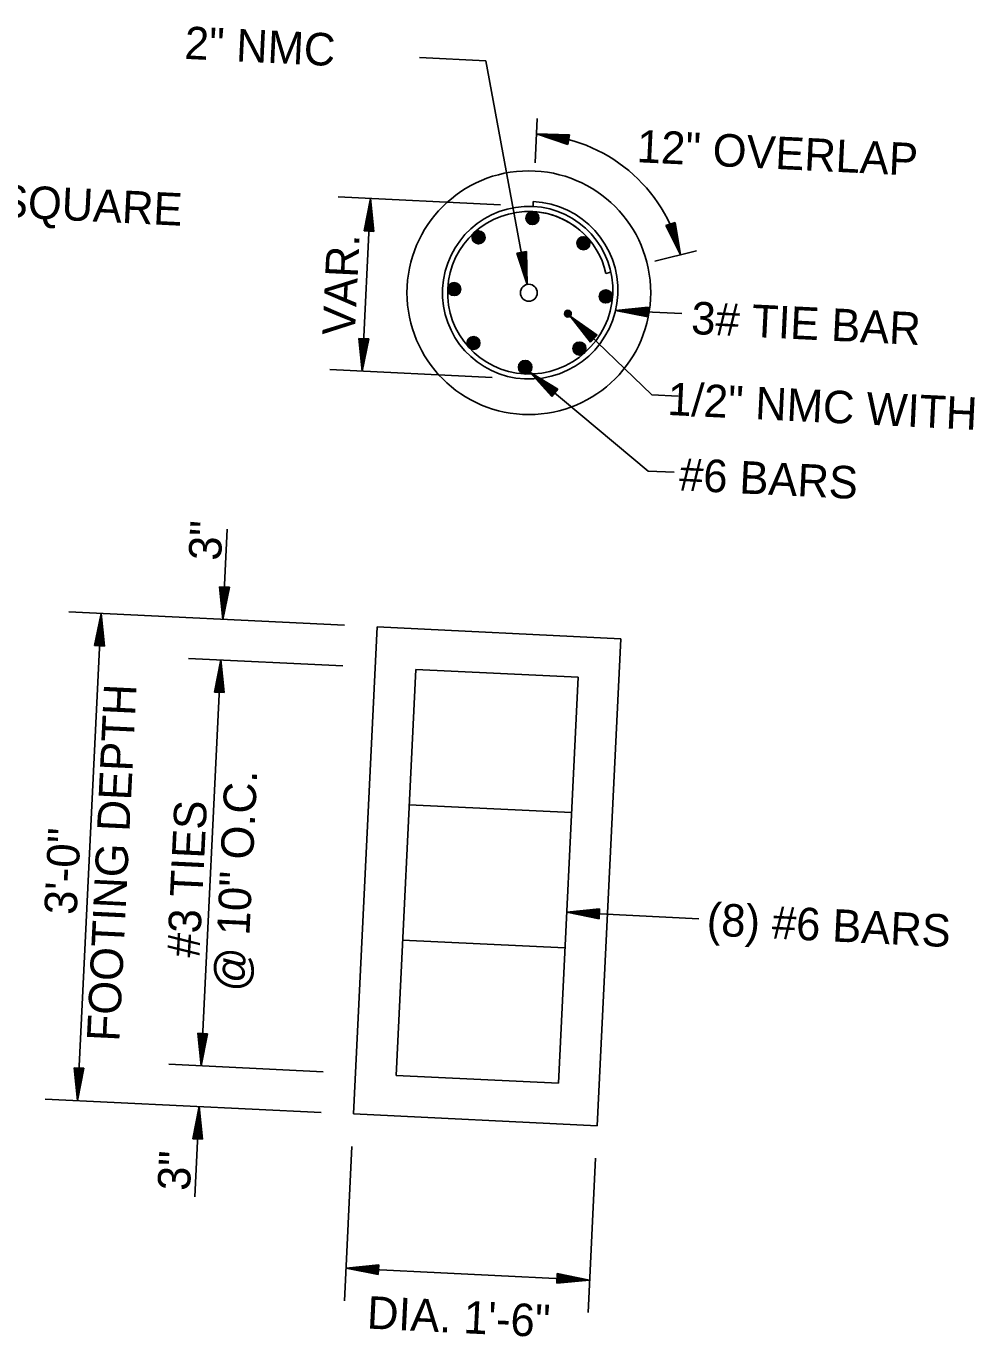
# Model space of a CAD drawing. Extents: x 661018 to 663325, y 642537 to 643074.
# Drawn here: x 662064.8 to 662163.6, y 642766 to 642901.8 of the extents above; entities that cross this region are included whole.
import ezdxf

# ---------------------------------------------------------------- set-up
doc = ezdxf.new("R2010")
doc.units = 0
doc.layers.add('R_Dimension', color=7, linetype='Continuous')

msp = doc.modelspace()

# ---------------------------------------------------------------- linework, layer by layer
at = {"layer": 'R_Dimension'}
for p, q in [((662105.59, 642898.58), (662112.48, 642898.24)), ((662116.77, 642875.08), (662112.48, 642898.24)), ((662117.58, 642887.68), (662117.8, 642892.28)), ((662120.96, 642889.59), (662117.73, 642890.67)), ((662121.14, 642890.58), (662117.73, 642890.67)), ((662120.97, 642889.67), (662118.28, 642890.57)), ((662121.12, 642890.5), (662118.28, 642890.57)), ((662121.11, 642890.41), (662118.85, 642890.47)), ((662120.99, 642889.75), (662118.85, 642890.47)), ((662121, 642889.84), (662119.41, 642890.38)), ((662121.09, 642890.33), (662119.41, 642890.38)), ((662120.96, 642889.59), (662121.14, 642890.58)), ((662121.08, 642890.25), (662119.97, 642890.28)), ((662121.02, 642889.92), (662119.97, 642890.28)), ((662121.06, 642890.16), (662120.52, 642890.18)), ((662121.03, 642890.01), (662120.52, 642890.18)), ((662114, 642883.32), (662097.17, 642884.14)), ((662099.67, 642866.09), (662100.53, 642883.97)), ((662099.87, 642880.63), (662100.53, 642883.97)), ((662100.88, 642880.58), (662100.53, 642883.97)), ((662117.36, 642883.16), (662117.39, 642883.68)), ((662099.95, 642880.63), (662100.51, 642883.41)), ((662100.04, 642880.63), (662100.48, 642882.83)), ((662100.12, 642880.62), (662100.45, 642882.27)), ((662100.62, 642880.6), (662100.45, 642882.27)), ((662100.71, 642880.59), (662100.48, 642882.83)), ((662100.79, 642880.59), (662100.51, 642883.41)), ((662116.63, 642881.96), (662117.36, 642882.63)), ((662116.64, 642882.08), (662117.24, 642882.63)), ((662116.64, 642881.85), (662117.47, 642882.61)), ((662116.66, 642881.76), (662117.56, 642882.58)), ((662116.69, 642882.25), (662117.07, 642882.59)), ((662116.69, 642881.67), (662117.64, 642882.54)), ((662116.73, 642881.6), (662117.71, 642882.49)), ((662116.78, 642881.53), (662117.78, 642882.43)), ((662116.84, 642881.47), (662117.83, 642882.37)), ((662116.9, 642881.41), (662117.88, 642882.3)), ((662116.98, 642881.37), (662117.92, 642882.22)), ((662100.21, 642880.62), (662100.42, 642881.7)), ((662100.29, 642880.61), (662100.4, 642881.14)), ((662100.45, 642880.61), (662100.4, 642881.14)), ((662100.54, 642880.6), (662100.42, 642881.7)), ((662117.06, 642881.33), (662117.95, 642882.14)), ((662117.15, 642881.3), (662117.97, 642882.04)), ((662117.26, 642881.28), (662117.98, 642881.93)), ((662117.39, 642881.29), (662117.96, 642881.8)), ((662117.58, 642881.34), (662117.89, 642881.62)), ((662132.09, 642881.5), (662131.13, 642881.19)), ((662131.13, 642881.19), (662132.66, 642878.14)), ((662131.21, 642881.21), (662132.48, 642878.68)), ((662131.29, 642881.24), (662132.3, 642879.23)), ((662131.37, 642881.27), (662132.13, 642879.76)), ((662131.45, 642881.29), (662131.95, 642880.3)), ((662131.53, 642881.32), (662131.77, 642880.84)), ((662131.68, 642881.37), (662131.77, 642880.84)), ((662131.76, 642881.39), (662131.95, 642880.3)), ((662131.85, 642881.42), (662132.13, 642879.76)), ((662131.93, 642881.45), (662132.3, 642879.23)), ((662132.01, 642881.48), (662132.48, 642878.68)), ((662132.09, 642881.5), (662132.66, 642878.14)), ((662099.87, 642880.63), (662100.88, 642880.58)), ((662111.05, 642880.02), (662111.72, 642880.63)), ((662111.05, 642879.9), (662111.84, 642880.62)), ((662111.06, 642879.8), (662111.93, 642880.59)), ((662111.08, 642880.16), (662111.58, 642880.62)), ((662111.09, 642879.71), (662112.02, 642880.56)), ((662111.13, 642879.63), (662112.1, 642880.51)), ((662111.17, 642879.56), (662112.16, 642880.46)), ((662111.19, 642880.38), (662111.35, 642880.52)), ((662111.23, 642879.5), (662112.22, 642880.4)), ((662111.29, 642879.44), (662112.28, 642880.34)), ((662111.36, 642879.39), (662112.32, 642880.26)), ((662111.43, 642879.34), (662112.35, 642880.18)), ((662111.52, 642879.31), (662112.38, 642880.09)), ((662111.62, 642879.29), (662112.39, 642879.99)), ((662111.74, 642879.28), (662112.39, 642879.87)), ((662111.89, 642879.3), (662112.35, 642879.72)), ((662121.91, 642879.32), (662122.68, 642880.02)), ((662121.92, 642879.44), (662122.56, 642880.03)), ((662121.92, 642879.22), (662122.78, 642880)), ((662121.95, 642879.59), (662122.41, 642880)), ((662121.95, 642879.13), (662122.87, 642879.96)), ((662121.98, 642879.05), (662122.95, 642879.92)), ((662122.03, 642878.97), (662123.02, 642879.87)), ((662122.08, 642878.91), (662123.08, 642879.81)), ((662122.14, 642878.85), (662123.13, 642879.75)), ((662122.21, 642878.79), (662123.18, 642879.67)), ((662122.28, 642878.75), (662123.21, 642879.59)), ((662122.37, 642878.71), (662123.24, 642879.51)), ((662116.67, 642878.49), (662115.68, 642878.31)), ((662115.68, 642878.31), (662116.77, 642875.08)), ((662115.76, 642878.32), (662116.67, 642875.63)), ((662115.84, 642878.34), (662116.57, 642876.2)), ((662115.93, 642878.35), (662116.47, 642876.76)), ((662116.01, 642878.37), (662116.37, 642877.32)), ((662116.1, 642878.38), (662116.27, 642877.87)), ((662116.25, 642878.41), (662116.27, 642877.87)), ((662116.34, 642878.43), (662116.37, 642877.32)), ((662116.42, 642878.44), (662116.47, 642876.76)), ((662116.5, 642878.46), (662116.57, 642876.2)), ((662116.59, 642878.47), (662116.67, 642875.63)), ((662116.67, 642878.49), (662116.77, 642875.08)), ((662122.47, 642878.69), (662123.26, 642879.41)), ((662122.58, 642878.68), (662123.26, 642879.29)), ((662122.72, 642878.69), (662123.23, 642879.15)), ((662122.95, 642878.78), (662123.12, 642878.94)), ((662134.29, 642878.55), (662130, 642877.48)), ((662125.43, 642876.34), (662124.91, 642876.21)), ((662108.51, 642874.54), (662109.3, 642875.26)), ((662108.52, 642874.66), (662109.19, 642875.27)), ((662108.53, 642874.44), (662109.4, 642875.23)), ((662108.54, 642874.8), (662109.04, 642875.25)), ((662108.56, 642874.35), (662109.48, 642875.2)), ((662108.59, 642874.27), (662109.56, 642875.15)), ((662108.64, 642874.2), (662109.63, 642875.1)), ((662108.67, 642875.03), (662108.8, 642875.15)), ((662108.69, 642874.14), (662109.69, 642875.04)), ((662108.75, 642874.08), (662109.74, 642874.97)), ((662108.82, 642874.03), (662109.79, 642874.9)), ((662108.9, 642873.98), (662109.82, 642874.82)), ((662108.99, 642873.95), (662109.85, 642874.73)), ((662109.09, 642873.93), (662109.86, 642874.63)), ((662109.2, 642873.92), (662109.85, 642874.51)), ((662109.35, 642873.94), (662109.82, 642874.36)), ((662124.23, 642873.87), (662124.92, 642874.5)), ((662124.23, 642873.76), (662125.03, 642874.49)), ((662124.25, 642874), (662124.79, 642874.49)), ((662124.25, 642873.66), (662125.13, 642874.46)), ((662124.27, 642873.57), (662125.21, 642874.43)), ((662124.31, 642873.5), (662125.29, 642874.38)), ((662124.33, 642874.2), (662124.59, 642874.43)), ((662124.36, 642873.42), (662125.35, 642874.33)), ((662124.41, 642873.36), (662125.41, 642874.27)), ((662124.48, 642873.3), (662125.46, 642874.2)), ((662124.55, 642873.25), (662125.5, 642874.12)), ((662124.63, 642873.21), (662125.54, 642874.04)), ((662124.72, 642873.18), (662125.56, 642873.95)), ((662124.82, 642873.16), (662125.57, 642873.84)), ((662124.94, 642873.16), (662125.56, 642873.72)), ((662125.1, 642873.19), (662125.52, 642873.57)), ((662129.3, 642872.73), (662125.91, 642872.39)), ((662129.26, 642871.73), (662129.3, 642872.73)), ((662120.63, 642872.07), (662120.99, 642872.4)), ((662120.64, 642871.97), (662121.09, 642872.38)), ((662120.67, 642872.23), (662120.83, 642872.37)), ((662120.67, 642871.88), (662121.18, 642872.34)), ((662120.72, 642871.82), (662121.24, 642872.29)), ((662120.78, 642871.76), (662121.29, 642872.22)), ((662120.87, 642871.72), (662121.32, 642872.13)), ((662120.97, 642871.7), (662121.33, 642872.03)), ((662121.14, 642871.74), (662121.27, 642871.86)), ((662121.21, 642871.79), (662129.69, 642863.63)), ((662123.31, 642869.1), (662121.21, 642871.79)), ((662124, 642869.83), (662121.21, 642871.79)), ((662123.36, 642869.16), (662121.62, 642871.4)), ((662123.94, 642869.77), (662121.62, 642871.4)), ((662125.91, 642872.39), (662132.8, 642872.06)), ((662129.26, 642871.73), (662125.91, 642872.39)), ((662129.3, 642872.65), (662126.48, 642872.37)), ((662129.26, 642871.81), (662126.48, 642872.37)), ((662129.3, 642872.56), (662127.06, 642872.34)), ((662129.26, 642871.9), (662127.06, 642872.34)), ((662129.29, 642872.48), (662127.62, 642872.31)), ((662129.27, 642871.98), (662127.62, 642872.31)), ((662129.29, 642872.39), (662128.19, 642872.28)), ((662129.27, 642872.07), (662128.19, 642872.28)), ((662129.28, 642872.31), (662128.75, 642872.26)), ((662129.28, 642872.15), (662128.75, 642872.26)), ((662123.88, 642869.71), (662122.04, 642871)), ((662123.42, 642869.22), (662122.04, 642871)), ((662123.48, 642869.28), (662122.45, 642870.61)), ((662123.83, 642869.64), (662122.45, 642870.61)), ((662123.77, 642869.58), (662122.86, 642870.22)), ((662123.54, 642869.34), (662122.86, 642870.22)), ((662099.32, 642869.48), (662099.67, 642866.09)), ((662100.33, 642869.43), (662099.32, 642869.48)), ((662099.41, 642869.48), (662099.69, 642866.66)), ((662099.49, 642869.48), (662099.72, 642867.23)), ((662099.58, 642869.47), (662099.75, 642867.79)), ((662099.66, 642869.47), (662099.78, 642868.37)), ((662100.33, 642869.43), (662099.67, 642866.09)), ((662100.25, 642869.44), (662099.69, 642866.66)), ((662100.16, 642869.44), (662099.72, 642867.23)), ((662099.75, 642869.46), (662099.8, 642868.93)), ((662100.08, 642869.45), (662099.75, 642867.79)), ((662099.99, 642869.45), (662099.78, 642868.37)), ((662099.91, 642869.46), (662099.8, 642868.93)), ((662110.51, 642868.98), (662111.28, 642869.68)), ((662110.52, 642869.1), (662111.16, 642869.68)), ((662110.53, 642868.88), (662111.38, 642869.65)), ((662110.55, 642868.79), (662111.47, 642869.62)), ((662110.56, 642869.25), (662111.01, 642869.66)), ((662110.59, 642868.7), (662111.55, 642869.58)), ((662110.63, 642868.63), (662111.62, 642869.53)), ((662110.68, 642868.56), (662111.68, 642869.47)), ((662110.74, 642868.5), (662111.73, 642869.4)), ((662110.81, 642868.45), (662111.78, 642869.33)), ((662110.89, 642868.41), (662111.82, 642869.25)), ((662110.97, 642868.37), (662111.84, 642869.16)), ((662111.07, 642868.35), (662111.86, 642869.06)), ((662111.18, 642868.34), (662111.86, 642868.95)), ((662111.32, 642868.35), (662111.83, 642868.81)), ((662121.49, 642868.51), (662122.17, 642869.12)), ((662121.49, 642868.39), (662122.28, 642869.11)), ((662121.51, 642868.29), (662122.38, 642869.08)), ((662121.52, 642868.65), (662122.02, 642869.1)), ((662121.54, 642868.2), (662122.46, 642869.05)), ((662121.57, 642868.12), (662122.54, 642869)), ((662121.62, 642868.05), (662122.61, 642868.95)), ((662121.65, 642868.87), (662121.79, 642869)), ((662121.67, 642867.99), (662122.67, 642868.89)), ((662121.73, 642867.93), (662122.72, 642868.82)), ((662121.8, 642867.88), (662122.76, 642868.75)), ((662121.88, 642867.83), (662122.8, 642868.67)), ((662123.71, 642869.52), (662123.27, 642869.83)), ((662123.6, 642869.41), (662123.27, 642869.83)), ((662123.31, 642869.1), (662124, 642869.83)), ((662111.55, 642868.44), (662111.72, 642868.59)), ((662121.97, 642867.8), (662122.83, 642868.58)), ((662122.07, 642867.78), (662122.84, 642868.48)), ((662122.18, 642867.77), (662122.83, 642868.36)), ((662122.33, 642867.79), (662122.8, 642868.21)), ((662113.13, 642865.44), (662096.3, 642866.26)), ((662115.85, 642866.47), (662116.65, 642867.2)), ((662115.86, 642866.59), (662116.53, 642867.21)), ((662115.86, 642866.37), (662116.75, 642867.18)), ((662115.89, 642866.74), (662116.39, 642867.19)), ((662115.89, 642866.28), (662116.84, 642867.14)), ((662115.92, 642866.2), (662116.92, 642867.1)), ((662115.96, 642866.12), (662116.99, 642867.05)), ((662116.01, 642866.05), (662117.05, 642867)), ((662116.06, 642867), (662116.1, 642867.05)), ((662116.07, 642865.99), (662117.11, 642866.93)), ((662116.14, 642865.94), (662117.16, 642866.86)), ((662116.21, 642865.89), (662117.2, 642866.78)), ((662116.29, 642865.85), (662117.23, 642866.7)), ((662116.39, 642865.82), (662117.25, 642866.6)), ((662116.49, 642865.81), (662117.25, 642866.5)), ((662116.62, 642865.81), (662117.24, 642866.37)), ((662116.78, 642865.84), (662117.19, 642866.21)), ((662117.03, 642865.99), (662129.3, 642855.74)), ((662119.3, 642863.45), (662117.03, 642865.99)), ((662119.94, 642864.22), (662117.03, 642865.99)), ((662119.35, 642863.51), (662117.46, 642865.63)), ((662119.89, 642864.16), (662117.46, 642865.63)), ((662119.84, 642864.09), (662117.91, 642865.26)), ((662119.41, 642863.58), (662117.91, 642865.26)), ((662119.46, 642863.64), (662118.34, 642864.9)), ((662119.78, 642864.03), (662118.34, 642864.9)), ((662119.73, 642863.96), (662118.78, 642864.53)), ((662119.52, 642863.71), (662118.78, 642864.53)), ((662119.67, 642863.9), (662119.21, 642864.17)), ((662119.57, 642863.77), (662119.21, 642864.17)), ((662119.3, 642863.45), (662119.94, 642864.22)), ((662129.69, 642863.63), (662132.39, 642863.5)), ((662129.3, 642855.74), (662132, 642855.61)), ((662085.22, 642840.37), (662085.68, 642849.73)), ((662084.88, 642843.76), (662085.22, 642840.37)), ((662085.89, 642843.72), (662084.88, 642843.76)), ((662084.97, 642843.76), (662085.25, 642840.94)), ((662085.05, 642843.76), (662085.28, 642841.52)), ((662085.14, 642843.75), (662085.31, 642842.08)), ((662085.22, 642843.75), (662085.33, 642842.65)), ((662085.89, 642843.72), (662085.22, 642840.37)), ((662085.81, 642843.72), (662085.25, 642840.94)), ((662085.72, 642843.72), (662085.28, 642841.52)), ((662085.31, 642843.74), (662085.36, 642843.21)), ((662085.64, 642843.73), (662085.31, 642842.08)), ((662085.55, 642843.73), (662085.33, 642842.65)), ((662085.47, 642843.74), (662085.36, 642843.21)), ((662097.84, 642839.76), (662069.24, 642841.15)), ((662070.15, 642790.51), (662072.6, 642840.99)), ((662071.93, 642837.65), (662072.6, 642840.99)), ((662072.02, 642837.64), (662072.58, 642840.43)), ((662072.86, 642837.6), (662072.58, 642840.43)), ((662072.94, 642837.6), (662072.6, 642840.99)), ((662072.1, 642837.64), (662072.55, 642839.85)), ((662072.19, 642837.63), (662072.52, 642839.29)), ((662072.69, 642837.61), (662072.52, 642839.29)), ((662072.77, 642837.61), (662072.55, 642839.85)), ((662098.76, 642789.12), (662101.21, 642839.6)), ((662101.21, 642839.6), (662126.45, 642838.37)), ((662071.93, 642837.65), (662072.94, 642837.6)), ((662072.28, 642837.63), (662072.49, 642838.72)), ((662072.36, 642837.63), (662072.47, 642838.15)), ((662072.52, 642837.62), (662072.47, 642838.15)), ((662072.6, 642837.61), (662072.49, 642838.72)), ((662124, 642787.89), (662126.45, 642838.37)), ((662097.64, 642835.55), (662081.65, 642836.33)), ((662082.98, 642794.1), (662085.02, 642836.17)), ((662084.35, 642832.83), (662085.02, 642836.17)), ((662085.36, 642832.78), (662085.02, 642836.17)), ((662084.43, 642832.82), (662084.99, 642835.61)), ((662084.52, 642832.82), (662084.96, 642835.03)), ((662085.19, 642832.79), (662084.96, 642835.03)), ((662085.28, 642832.78), (662084.99, 642835.61)), ((662103.17, 642793.12), (662105.21, 642835.19)), ((662122.04, 642834.37), (662105.21, 642835.19)), ((662084.6, 642832.81), (662084.94, 642834.47)), ((662084.69, 642832.81), (662084.91, 642833.9)), ((662084.78, 642832.81), (662084.88, 642833.33)), ((662084.93, 642832.8), (662084.88, 642833.33)), ((662085.02, 642832.79), (662084.91, 642833.9)), ((662085.11, 642832.79), (662084.94, 642834.47)), ((662119.99, 642792.3), (662122.04, 642834.37)), ((662084.35, 642832.83), (662085.36, 642832.78)), ((662121.36, 642820.35), (662104.53, 642821.17)), ((662124.25, 642810.36), (662120.86, 642810.02)), ((662124.25, 642810.27), (662121.42, 642809.99)), ((662124.2, 642809.35), (662124.25, 642810.36)), ((662124.2, 642809.35), (662120.86, 642810.02)), ((662120.86, 642810.02), (662134.56, 642809.35)), ((662124.21, 642809.43), (662121.42, 642809.99)), ((662124.24, 642810.19), (662122, 642809.96)), ((662124.21, 642809.52), (662122, 642809.96)), ((662124.24, 642810.1), (662122.56, 642809.93)), ((662124.21, 642809.6), (662122.56, 642809.93)), ((662124.23, 642810.02), (662123.13, 642809.9)), ((662124.22, 642809.69), (662123.13, 642809.9)), ((662124.23, 642809.93), (662123.69, 642809.88)), ((662124.22, 642809.77), (662123.69, 642809.88)), ((662120.67, 642806.33), (662103.85, 642807.14)), ((662082.63, 642797.49), (662082.98, 642794.1)), ((662083.64, 642797.44), (662082.63, 642797.49)), ((662082.72, 642797.49), (662083, 642794.66)), ((662082.8, 642797.48), (662083.03, 642795.24)), ((662082.89, 642797.48), (662083.06, 642795.8)), ((662082.97, 642797.48), (662083.09, 642796.37)), ((662083.64, 642797.44), (662082.98, 642794.1)), ((662083.56, 642797.45), (662083, 642794.66)), ((662083.47, 642797.45), (662083.03, 642795.24)), ((662083.06, 642797.47), (662083.11, 642796.94)), ((662083.39, 642797.45), (662083.06, 642795.8)), ((662083.3, 642797.46), (662083.09, 642796.37)), ((662083.22, 642797.46), (662083.11, 642796.94)), ((662095.6, 642793.49), (662079.61, 642794.27)), ((662069.81, 642793.9), (662070.15, 642790.51)), ((662070.82, 642793.85), (662069.81, 642793.9)), ((662069.89, 642793.89), (662070.18, 642791.07)), ((662069.98, 642793.89), (662070.21, 642791.65)), ((662070.06, 642793.89), (662070.23, 642792.21)), ((662070.15, 642793.88), (662070.26, 642792.78)), ((662070.82, 642793.85), (662070.15, 642790.51)), ((662070.74, 642793.85), (662070.18, 642791.07)), ((662070.65, 642793.86), (662070.21, 642791.65)), ((662070.57, 642793.86), (662070.23, 642792.21)), ((662070.24, 642793.88), (662070.29, 642793.34)), ((662070.48, 642793.87), (662070.26, 642792.78)), ((662070.39, 642793.87), (662070.29, 642793.34)), ((662119.99, 642792.3), (662103.17, 642793.12)), ((662095.39, 642789.28), (662066.79, 642790.67)), ((662082.1, 642786.55), (662082.77, 642789.9)), ((662082.32, 642780.54), (662082.77, 642789.9)), ((662083.11, 642786.51), (662082.77, 642789.9)), ((662082.19, 642786.55), (662082.74, 642789.33)), ((662082.27, 642786.55), (662082.72, 642788.75)), ((662082.94, 642786.51), (662082.72, 642788.75)), ((662083.03, 642786.51), (662082.74, 642789.33)), ((662124, 642787.89), (662098.76, 642789.12)), ((662082.36, 642786.54), (662082.69, 642788.19)), ((662082.44, 642786.54), (662082.66, 642787.62)), ((662082.77, 642786.52), (662082.66, 642787.62)), ((662082.86, 642786.52), (662082.69, 642788.19)), ((662082.1, 642786.55), (662083.11, 642786.51)), ((662082.53, 642786.53), (662082.63, 642787.06)), ((662082.69, 642786.53), (662082.63, 642787.06)), ((662098.59, 642785.75), (662097.82, 642769.77)), ((662123.83, 642784.53), (662123.06, 642768.54)), ((662101.37, 642773.48), (662097.98, 642773.13)), ((662123.22, 642771.91), (662097.98, 642773.13)), ((662101.32, 642772.47), (662097.98, 642773.13)), ((662101.37, 642773.39), (662098.54, 642773.11)), ((662101.33, 642772.55), (662098.54, 642773.11)), ((662101.36, 642773.31), (662099.12, 642773.08)), ((662101.33, 642772.64), (662099.12, 642773.08)), ((662101.36, 642773.22), (662099.68, 642773.05)), ((662101.33, 642772.72), (662099.68, 642773.05)), ((662101.35, 642773.14), (662100.25, 642773.02)), ((662101.34, 642772.81), (662100.25, 642773.02)), ((662101.35, 642773.05), (662100.81, 642773)), ((662101.34, 642772.89), (662100.81, 642773)), ((662101.32, 642772.47), (662101.37, 642773.48)), ((662119.88, 642772.58), (662119.83, 642771.57)), ((662119.86, 642772.23), (662120.95, 642772.02)), ((662119.87, 642772.49), (662122.66, 642771.94)), ((662119.87, 642772.41), (662122.08, 642771.96)), ((662119.87, 642772.32), (662121.52, 642771.99)), ((662119.88, 642772.58), (662123.22, 642771.91)), ((662119.83, 642771.65), (662122.66, 642771.94)), ((662119.83, 642771.57), (662123.22, 642771.91)), ((662119.84, 642771.82), (662121.52, 642771.99)), ((662119.84, 642771.74), (662122.08, 642771.96)), ((662119.85, 642771.99), (662120.39, 642772.05)), ((662119.85, 642771.91), (662120.95, 642772.02)), ((662119.86, 642772.15), (662120.39, 642772.05))]:
    msp.add_line(p, q, dxfattribs=at)
for centre, radius in [((662116.93, 642874.22), 12.63), ((662117.3, 642881.96), 0.674), ((662111.72, 642879.96), 0.674), ((662122.59, 642879.35), 0.674), ((662109.19, 642874.59), 0.674), ((662116.93, 642874.22), 0.877), ((662124.9, 642873.83), 0.674), ((662120.98, 642872.05), 0.351), ((662111.19, 642869.01), 0.674), ((662122.17, 642868.44), 0.674), ((662116.55, 642866.5), 0.702)]:
    msp.add_circle(centre, radius, dxfattribs=at)
for centre, radius, start, end in [((662116.94, 642874.48), 16.14, 13.1138, 87.2199), ((662116.94, 642874.48), 9.21, 267.2199, 87.2199), ((662116.93, 642874.22), 8.95, 87.2199, 267.2199), ((662116.93, 642874.22), 8.42, 87.2199, 267.2199), ((662116.94, 642874.48), 8.69, 267.2199, 87.2199), ((662116.94, 642874.48), 8.16, 40.9093, 87.2199), ((662116.94, 642874.48), 8.16, 12.2362, 87.2199)]:
    msp.add_arc(centre, radius, start, end, dxfattribs=at)

# ---------------------------------------------------------------- texts
for s, height, rotation, p in [('2" NMC', 3.369, 357.2199, (662081.19, 642898.46)), ('12" OVERLAP', 3.3692, 357.2199, (662128.06, 642887.75)), ('ANCHOR BASE SQUARE', 3.3692, 357.2199, (662027.94, 642883.73)), ('VAR.', 3.369, 87.2199, (662098.89, 642869.73)), ('3# TIE BAR', 3.369, 357.2199, (662133.7, 642869.95)), (' 1/2" NMC WITH A SOLID 1C/#8 A.W.G., E.G.C.', 3.3692, 357.2199, (662129.98, 642861.62)), ('#6 BARS', 3.369, 357.2199, (662132.44, 642853.74)), ('3"', 3.369, 87.2199, (662085.02, 642846.41)), ('FOOTING DEPTH', 3.3692, 87.2199, (662074.48, 642796.58)), ('@ 10" O.C.', 3.369, 87.2199, (662087.68, 642801.75)), ('#3 TIES', 3.369, 87.2199, (662082.79, 642805.28)), ('3\'-0"', 3.369, 87.2199, (662070.06, 642809.71)), ('(8) #6 BARS', 3.3692, 357.2199, (662135.31, 642807.63)), ('3"', 3.369, 87.2199, (662081.8, 642781.11)), ('DIA. 1\'-6"', 3.369, 357.2199, (662100.1, 642766.89))]:
    msp.add_text(s, height=height, rotation=rotation, dxfattribs=at).set_placement(p)

doc.saveas('drawing.dxf')
